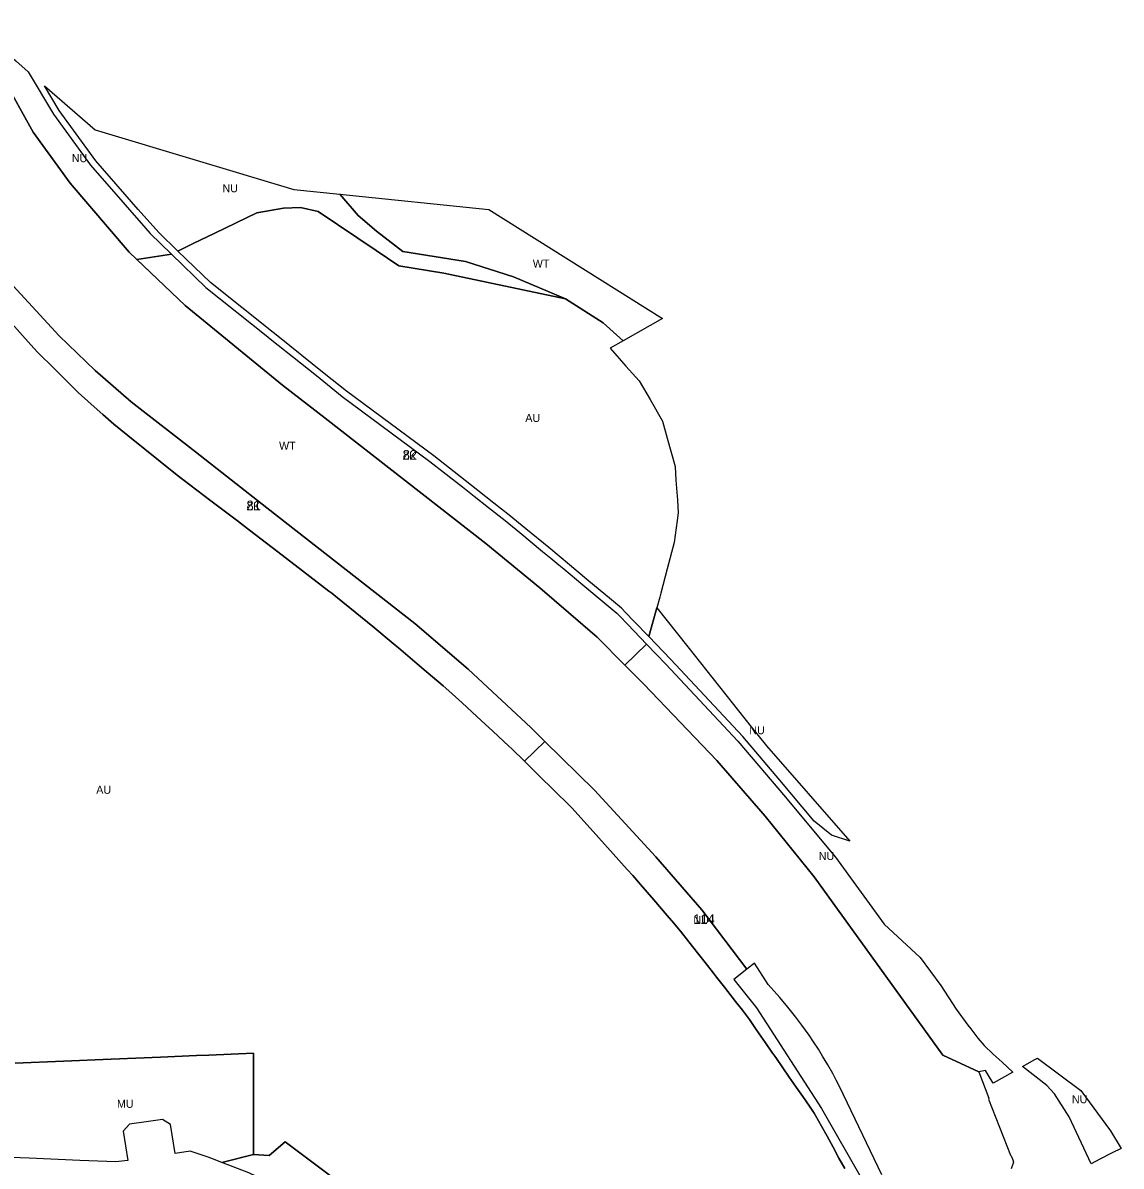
# Model space of a CAD drawing. Extents: x -535894 to -532834, y -1165802 to -1163647.
# Drawn here: x -533682 to -532996, y -1164811 to -1164097 of the extents above; entities that cross this region are included whole.
import ezdxf

# ---------------------------------------------------------------- set-up
doc = ezdxf.new("R2010")
doc.units = 0
for name, color, linetype in [('Vrstva 16', 7, 'Continuous'), ('Vrstva 17', 7, 'Continuous'), ('Vrstva 19', 7, 'Continuous'), ('Vrstva 20', 7, 'Continuous'), ('Vrstva 22', 7, 'Continuous'), ('Vrstva 34', 7, 'Continuous'), ('Vrstva 4', 7, 'Continuous'), ('Vrstva 61', 7, 'Continuous')]:
    doc.layers.add(name, color=color, linetype=linetype)

msp = doc.modelspace()

# ---------------------------------------------------------------- linework, layer by layer
at = {"layer": 'Vrstva 16'}
msp.add_lwpolyline([(-533449.329, -1164857.017), (-533482.547, -1164842.741), (-533485.98, -1164841.17), (-533502.187, -1164833.429), (-533508.929, -1164830.209), (-533541.19, -1164814.8), (-533557.97, -1164808.32), (-533538.206, -1164803.326), (-533528.49, -1164803.93), (-533518.46, -1164795.33), (-533502.549, -1164807.296), (-533491.019, -1164815.967), (-533479.52, -1164834.02), (-533476.1, -1164835.72), (-533476.589, -1164836.253)], close=True, dxfattribs=at)
at = {"layer": 'Vrstva 17'}
msp.add_lwpolyline([(-533589.48, -1164241.027), (-533567.95, -1164261.82), (-533530.25, -1164291.87), (-533527.78, -1164293.84), (-533508.97, -1164308.83), (-533498.95, -1164316.9), (-533482.76, -1164329.92), (-533428.16, -1164370.44), (-533407.7, -1164386.45), (-533400.38, -1164392.18), (-533391.36, -1164399.24), (-533381.09, -1164407.28), (-533371.94, -1164414.84), (-533357.65, -1164426.65), (-533352.45, -1164430.94), (-533347.48, -1164435.05), (-533344.43, -1164437.59), (-533332.48, -1164447.55), (-533320, -1164457.95), (-533311.26, -1164465.24), (-533309.57, -1164466.99), (-533304.36, -1164472.39), (-533292.65, -1164484.53), (-533306.34, -1164497.645), (-533323.6, -1164480.19), (-533359.31, -1164449.39), (-533393.01, -1164421.73), (-533493.52, -1164343.51), (-533520.08, -1164322.87), (-533580.88, -1164273.2), (-533611.129, -1164244.351)], close=True, dxfattribs=at)
msp.add_lwpolyline([(-533688.28, -1164260.76), (-533659.7, -1164292.03), (-533637.12, -1164313.74), (-533614.65, -1164333.34), (-533574.57, -1164364.55), (-533529.97, -1164399.56), (-533437.52, -1164471.63), (-533404.17, -1164500.26), (-533365.03, -1164536.67), (-533356.161, -1164545.372), (-533369.01, -1164557.68), (-533376.87, -1164549.96), (-533378.75, -1164548.22), (-533388.71, -1164539.01), (-533393.52, -1164534.57), (-533398.68, -1164529.8), (-533407.83, -1164521.35), (-533416.13, -1164513.68), (-533419.75, -1164510.6), (-533433.01, -1164499.36), (-533447.72, -1164486.86), (-533449.65, -1164485.24), (-533463.74, -1164473.66), (-533485.66, -1164455.66), (-533489.36, -1164452.83), (-533491.1, -1164451.5), (-533507.65, -1164438.78), (-533522.97, -1164427.03), (-533540.77, -1164413.38), (-533548.26, -1164407.66), (-533564.8, -1164395.06), (-533582.28, -1164381.75), (-533585.87, -1164379.01), (-533616.81, -1164354.28), (-533625.55, -1164347.3), (-533632.43, -1164341.14), (-533639.6, -1164334.73), (-533647.79, -1164327.4), (-533662.64, -1164312.76), (-533673.2, -1164302.34), (-533677.32, -1164297.76), (-533701.48, -1164270.84)], dxfattribs=at)
at = {"layer": 'Vrstva 19'}
for points in [[(-533615.89, -1164239.81), (-533652.75, -1164196.64), (-533675.79, -1164164.9), (-533714.01, -1164096.6), (-533693.46, -1164114.46), (-533686.62, -1164120.4), (-533678.92, -1164127.1), (-533663.1, -1164153.72), (-533640.06, -1164185.46), (-533618.43, -1164210.24), (-533605.59, -1164224.96), (-533602.74, -1164228.22), (-533589.48, -1164241.027), (-533611.129, -1164244.351)], [(-533375.76, -1164255.2), (-533343.32, -1164268.94), (-533419.39, -1164252.85), (-533447.47, -1164248.27), (-533461.562, -1164238.775), (-533497.797, -1164214.361), (-533508.828, -1164211.815), (-533519.496, -1164212.422), (-533536.104, -1164215.21), (-533562.456, -1164227.956), (-533575.957, -1164234.486), (-533585.451, -1164239.078), (-533597.315, -1164227.62), (-533610.265, -1164213.212), (-533636.772, -1164182.84), (-533659.588, -1164151.409), (-533668.817, -1164135.879), (-533637.25, -1164163.31), (-533513.14, -1164200.59), (-533484.246, -1164203.579), (-533472.74, -1164216.82), (-533461.34, -1164226.64), (-533445.02, -1164239.39), (-533405.72, -1164245.67)], [(-533165.64, -1164607.65), (-533177.04, -1164603.82), (-533187.972, -1164595.15), (-533209.403, -1164569.613), (-533232.543, -1164542.376), (-533277.572, -1164494.141), (-533291.333, -1164479.846), (-533286.31, -1164461.99), (-533266.97, -1164486.26), (-533227.22, -1164536.15), (-533217.69, -1164548.05)], [(-533177.92, -1164613.75), (-533174.61, -1164617.7), (-533144.204, -1164659.543), (-533121.714, -1164680.309), (-533108.898, -1164697.684), (-533099.18, -1164712.521), (-533091.952, -1164722.472), (-533090.161, -1164724.938), (-533085.762, -1164730.682), (-533081.802, -1164735.237), (-533076.175, -1164740.567), (-533070.523, -1164745.61), (-533063.86, -1164751.81), (-533076.17, -1164758.76), (-533079.04, -1164754), (-533080.974, -1164750.789), (-533085.07, -1164751.78), (-533107.67, -1164741.3), (-533187.88, -1164629.82), (-533218.62, -1164591.93), (-533248.86, -1164557.23), (-533294.45, -1164509.67), (-533306.34, -1164497.645), (-533292.65, -1164484.53), (-533280.62, -1164497.03), (-533235.68, -1164545.17), (-533205.86, -1164580.27)], [(-533057.72, -1164748.344), (-533050.15, -1164744.07), (-533048.53, -1164743.15), (-533021.38, -1164763.26), (-533002.77, -1164788.53), (-532996.17, -1164799.59), (-533001.68, -1164802.19), (-533009.419, -1164806.211), (-533014.98, -1164809.1), (-533028.64, -1164779.86), (-533037.824, -1164765.421), (-533042.687, -1164760.287)]]:
    msp.add_lwpolyline(points, close=True, dxfattribs=at)
at = {"layer": 'Vrstva 20'}
msp.add_lwpolyline([(-533168.77, -1164812.17), (-533172.45, -1164805.52), (-533176.14, -1164798.83), (-533179.93, -1164791.97), (-533183.43, -1164785.63), (-533187.14, -1164778.93), (-533187.91, -1164777.51), (-533190.93, -1164773.16), (-533195.08, -1164767.19), (-533199.21, -1164761.24), (-533203.5, -1164755.07), (-533207.59, -1164749.17), (-533212, -1164742.81), (-533214.36, -1164739.41), (-533218.37, -1164733.63), (-533224.16, -1164725.28), (-533228.43, -1164719.12), (-533230.18, -1164716.6), (-533232.82, -1164713.23), (-533237.07, -1164707.79), (-533241.91, -1164701.61), (-533244.066, -1164698.853), (-533249.02, -1164692.52), (-533250.95, -1164690.07), (-533256.12, -1164683.46), (-533263.96, -1164673.42), (-533271.44, -1164663.87), (-533272.67, -1164662.3), (-533275.61, -1164658.9), (-533279.79, -1164654.05), (-533288.14, -1164644.37), (-533296.52, -1164634.66), (-533301.29, -1164629.13), (-533304.78, -1164625.25), (-533313.54, -1164615.51), (-533322.44, -1164605.61), (-533339.13, -1164587.05), (-533340.54, -1164585.66), (-533350.43, -1164575.94), (-533359.97, -1164566.56), (-533369.01, -1164557.68), (-533356.161, -1164545.372), (-533325.21, -1164575.74), (-533286.88, -1164617.4), (-533258.18, -1164650.51), (-533230.072, -1164687.654), (-533238.085, -1164694.066), (-533224.07, -1164711.63), (-533183.34, -1164774.65), (-533157.83, -1164819.27)], dxfattribs=at)
at = {"layer": 'Vrstva 22'}
msp.add_lwpolyline([(-533585.451, -1164239.078), (-533575.957, -1164234.486), (-533562.456, -1164227.956), (-533536.104, -1164215.21), (-533519.496, -1164212.422), (-533508.828, -1164211.815), (-533497.797, -1164214.361), (-533461.562, -1164238.775), (-533447.47, -1164248.27), (-533419.39, -1164252.85), (-533343.32, -1164268.94), (-533319.79, -1164283.92), (-533307.29, -1164295.19), (-533315.38, -1164299.76), (-533305.71, -1164310.91), (-533297.21, -1164320.14), (-533290.4, -1164331.87), (-533282.74, -1164345.28), (-533279.76, -1164355.99), (-533274.89, -1164373.76), (-533274.29, -1164382.26), (-533273.41, -1164394.65), (-533272.85, -1164402.66), (-533273.53, -1164407.35), (-533275.5, -1164421.12), (-533279.71, -1164437.57), (-533283.68, -1164452.7), (-533284.39, -1164455.19), (-533286.31, -1164461.99), (-533291.333, -1164479.846), (-533300.609, -1164470.229), (-533305.535, -1164465.123), (-533308.396, -1164462.16), (-533315.918, -1164455.886), (-533328.75, -1164445.191), (-533340.821, -1164435.131), (-533353.78, -1164424.22), (-533368.067, -1164412.578), (-533378.457, -1164404.007), (-533388.004, -1164396.533), (-533398.112, -1164388.622), (-533406.098, -1164382.371), (-533425.614, -1164367.099), (-533480.192, -1164326.596), (-533493.982, -1164315.505), (-533523.075, -1164292.219), (-533525.901, -1164289.966), (-533565.176, -1164258.66)], close=True, dxfattribs=at)
for points in [[(-533701.48, -1164270.84), (-533677.32, -1164297.76), (-533673.2, -1164302.34), (-533662.64, -1164312.76), (-533647.79, -1164327.4), (-533639.6, -1164334.73), (-533632.43, -1164341.14), (-533625.55, -1164347.3), (-533616.81, -1164354.28), (-533585.87, -1164379.01), (-533582.28, -1164381.75), (-533564.8, -1164395.06), (-533548.26, -1164407.66), (-533540.77, -1164413.38), (-533522.97, -1164427.03), (-533507.65, -1164438.78), (-533491.1, -1164451.5), (-533489.36, -1164452.83), (-533485.66, -1164455.66), (-533463.74, -1164473.66), (-533449.65, -1164485.24), (-533447.72, -1164486.86), (-533433.01, -1164499.36), (-533419.75, -1164510.6), (-533416.13, -1164513.68), (-533407.83, -1164521.35), (-533398.68, -1164529.8), (-533393.52, -1164534.57), (-533388.71, -1164539.01), (-533378.75, -1164548.22), (-533376.87, -1164549.96), (-533369.01, -1164557.68), (-533359.97, -1164566.56), (-533350.43, -1164575.94), (-533340.54, -1164585.66), (-533339.13, -1164587.05), (-533322.44, -1164605.61), (-533313.54, -1164615.51), (-533304.78, -1164625.25), (-533301.29, -1164629.13), (-533296.52, -1164634.66), (-533288.14, -1164644.37), (-533279.79, -1164654.05), (-533275.61, -1164658.9), (-533272.67, -1164662.3), (-533271.44, -1164663.87), (-533263.96, -1164673.42), (-533256.12, -1164683.46), (-533250.95, -1164690.07), (-533249.02, -1164692.52), (-533244.066, -1164698.853), (-533241.91, -1164701.61), (-533237.07, -1164707.79), (-533232.82, -1164713.23), (-533230.18, -1164716.6), (-533228.43, -1164719.12), (-533224.16, -1164725.28), (-533218.37, -1164733.63), (-533214.36, -1164739.41), (-533212, -1164742.81), (-533207.59, -1164749.17), (-533203.5, -1164755.07), (-533199.21, -1164761.24), (-533195.08, -1164767.19), (-533190.93, -1164773.16), (-533187.91, -1164777.51), (-533187.14, -1164778.93), (-533183.43, -1164785.63), (-533179.93, -1164791.97), (-533176.14, -1164798.83), (-533172.45, -1164805.52), (-533168.77, -1164812.17)], [(-533491.019, -1164815.967), (-533502.549, -1164807.296), (-533518.46, -1164795.33), (-533528.49, -1164803.93), (-533538.206, -1164803.326), (-533538.206, -1164787.55), (-533538.206, -1164767.331), (-533538.206, -1164740.045), (-533566.117, -1164741.224), (-533573.781, -1164741.547), (-533596.399, -1164742.502), (-533627.184, -1164743.802), (-533656.85, -1164745.055), (-533687.212, -1164746.337)]]:
    msp.add_lwpolyline(points, dxfattribs=at)
at = {"layer": 'Vrstva 34'}
msp.add_lwpolyline([(-533687.212, -1164746.337), (-533656.85, -1164745.055), (-533627.184, -1164743.802), (-533596.399, -1164742.502), (-533573.781, -1164741.547), (-533566.117, -1164741.224), (-533538.206, -1164740.045), (-533538.206, -1164767.331), (-533538.206, -1164787.55), (-533538.206, -1164803.326), (-533557.97, -1164808.32), (-533563.91, -1164806.02), (-533566.47, -1164805.04), (-533577.82, -1164801.33), (-533587.26, -1164802.74), (-533590.019, -1164784.558), (-533595.101, -1164781.443), (-533605.393, -1164782.913), (-533615.685, -1164784.383), (-533619.617, -1164788.714), (-533616.74, -1164806.99), (-533624.24, -1164808.01), (-533646.8, -1164807.03), (-533678.4, -1164805.66), (-533695.1, -1164804.93)], dxfattribs=at)
at = {"layer": 'Vrstva 4'}
for points in [[(-533714.01, -1164096.6), (-533675.79, -1164164.9), (-533652.75, -1164196.64), (-533615.89, -1164239.81), (-533580.88, -1164273.2), (-533520.08, -1164322.87), (-533493.52, -1164343.51), (-533393.01, -1164421.73), (-533359.31, -1164449.39), (-533323.6, -1164480.19), (-533306.34, -1164497.645), (-533294.45, -1164509.67), (-533248.86, -1164557.23), (-533218.62, -1164591.93), (-533187.88, -1164629.82), (-533107.67, -1164741.3), (-533085.07, -1164751.78), (-533078.92, -1164768.23), (-533078.96, -1164768.7), (-533065.26, -1164803.77), (-533064.85, -1164804.08), (-533063.85, -1164806.75), (-533063.41, -1164808.03), (-533064.98, -1164812.34)], [(-533145.683, -1164816.04), (-533171.85, -1164761.354), (-533174.141, -1164756.895), (-533176.389, -1164752.709), (-533179.464, -1164747.253), (-533182.674, -1164741.852), (-533185.298, -1164737.639), (-533188.351, -1164732.944), (-533191.148, -1164728.822), (-533195.682, -1164722.466), (-533199.44, -1164717.478), (-533204.377, -1164711.27), (-533209.409, -1164705.307), (-533216.777, -1164697.165), (-533225.204, -1164683.758), (-533230.072, -1164687.654), (-533258.18, -1164650.51), (-533286.88, -1164617.4), (-533325.21, -1164575.74), (-533356.161, -1164545.372), (-533365.03, -1164536.67), (-533404.17, -1164500.26), (-533437.52, -1164471.63), (-533529.97, -1164399.56), (-533574.57, -1164364.55), (-533614.65, -1164333.34), (-533637.12, -1164313.74), (-533659.7, -1164292.03), (-533688.28, -1164260.76)]]:
    msp.add_lwpolyline(points, dxfattribs=at)
msp.add_lwpolyline([(-533405.72, -1164245.67), (-533445.02, -1164239.39), (-533461.34, -1164226.64), (-533472.74, -1164216.82), (-533484.246, -1164203.579), (-533391.15, -1164213.21), (-533282.63, -1164281.27), (-533307.29, -1164295.19), (-533319.79, -1164283.92), (-533343.32, -1164268.94), (-533375.76, -1164255.2)], close=True, dxfattribs=at)

# ---------------------------------------------------------------- texts
at = {"layer": 'Vrstva 17'}
for rotation, p in [(360, (-533444.9911, -1164369.336)), (0.0000001, (-533542.5984, -1164400.9725))]:
    msp.add_text('ZK', height=5, rotation=rotation, dxfattribs=at).set_placement(p)
at = {"layer": 'Vrstva 19'}
for rotation, p in [(360, (-533651.745, -1164183.5899)), (360, (-533557.6221, -1164202.4095)), (0, (-533228.4865, -1164540.8556)), (0.0000001, (-533185.1, -1164619.4151)), (360, (-533026.945, -1164771.3131))]:
    msp.add_text('NU', height=5, rotation=rotation, dxfattribs=at).set_placement(p)
at = {"layer": 'Vrstva 20'}
msp.add_text('NU', height=5, rotation=360, dxfattribs=at).set_placement((-533263.42, -1164659.2882))
at = {"layer": 'Vrstva 22'}
for rotation, p in [(0.0000001, (-533368.4301, -1164345.8305)), (359.9999999, (-533636.4907, -1164578.046))]:
    msp.add_text('AU', height=5, rotation=rotation, dxfattribs=at).set_placement(p)
at = {"layer": 'Vrstva 34'}
msp.add_text('MU', height=5, rotation=360, dxfattribs=at).set_placement((-533623.5341, -1164774.1825))
at = {"layer": 'Vrstva 4'}
for rotation, p in [(360, (-533363.7566, -1164249.3845)), (0.0000001, (-533522.2549, -1164363.205))]:
    msp.add_text('WT', height=5, rotation=rotation, dxfattribs=at).set_placement(p)
at = {"layer": 'Vrstva 61'}
for s, rotation, p in [('82', 360, (-533444.9911, -1164369.336)), ('81', 0, (-533542.5984, -1164400.9725)), ('114', 0, (-533263.42, -1164659.2882))]:
    msp.add_text(s, height=6, rotation=rotation, dxfattribs=at).set_placement(p)

doc.saveas('drawing.dxf')
